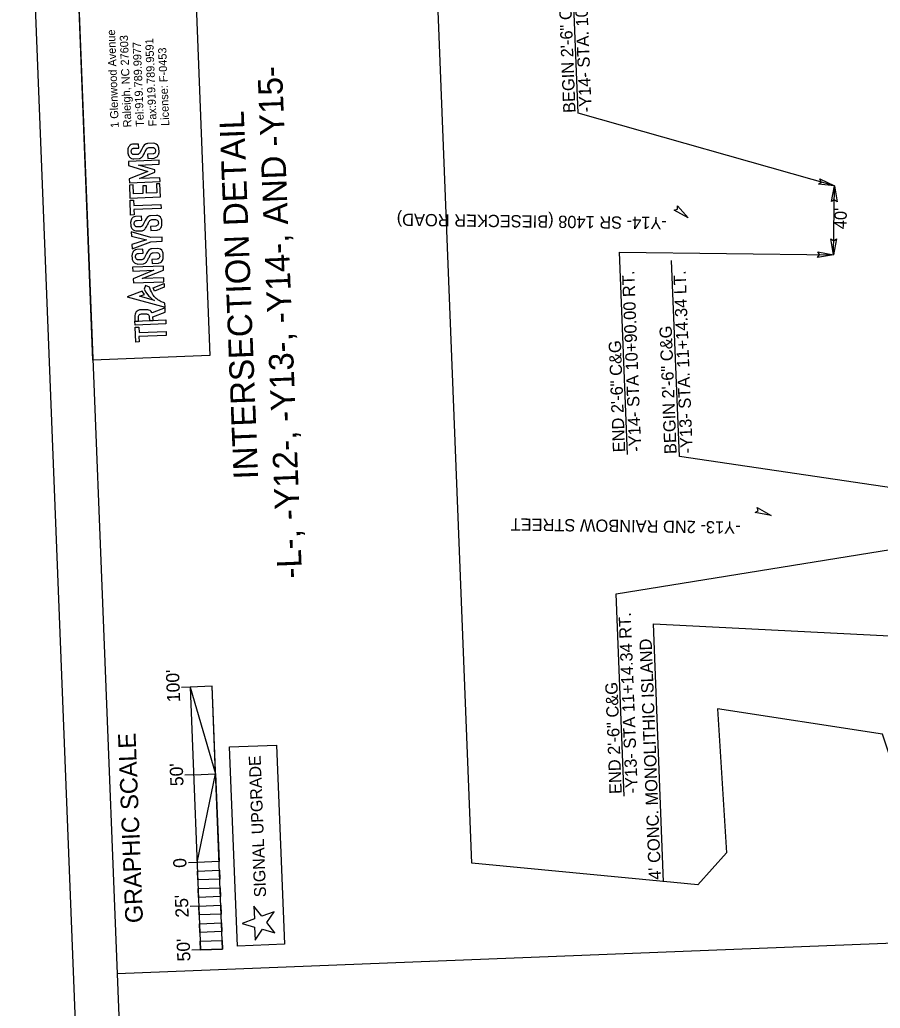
# Model space of a CAD drawing. Extents: x 1627811 to 1628977, y 762656 to 764629.
# Drawn here: x 1627811 to 1628301, y 763561 to 764125 of the extents above; entities that cross this region are included whole.
import ezdxf

# ---------------------------------------------------------------- set-up
doc = ezdxf.new("R2010")
doc.units = 0
for name, color, linetype in [('Old_Level_2', 7, 'Continuous'), ('Old_Level_58', 7, 'Continuous'), ('Prop Dimension', 7, 'Continuous'), ('Prop Dimension Text', 7, 'Continuous'), ('Prop DSN Text', 7, 'Continuous'), ('Prop Grid Mask', 7, 'Continuous'), ('Prop RDY Traffic Signal CELL', 7, 'Continuous'), ('Prop Terminator CELL', 7, 'Continuous'), ('Sheet Clip Boundary CELL', 7, 'Continuous'), ('Sheet Data Field CELL', 7, 'Continuous'), ('Sheet Plan And Profile CELL', 7, 'Continuous'), ('Sheet Plot Border Outside CELL', 7, 'Continuous'), ('Sheet Title CELL', 7, 'Continuous')]:
    doc.layers.add(name, color=color, linetype=linetype)

msp = doc.modelspace()

# ---------------------------------------------------------------- linework, layer by layer
at = {"layer": 'Old_Level_58'}
msp.add_lwpolyline([(1627852.24, 763930.86), (1627844.36, 764130.75), (1627911, 764133.38), (1627918.88, 763933.48)], close=True, dxfattribs=at)
at = {"layer": 'Prop Dimension'}
for p, q in [((1628128.8, 764071.76), (1628124.45, 764182.17)), ((1628274.83, 764030.25), (1628128.8, 764071.76)), ((1628274.32, 763990.99), (1628274.83, 764030.25)), ((1628156.94, 763877.1), (1628152.39, 763992.54)), ((1628152.39, 763992.54), (1628274.32, 763990.99)), ((1628186.47, 763876.05), (1628182.06, 763987.72)), ((1628343.52, 763852.84), (1628186.47, 763876.05)), ((1628150.43, 763797.78), (1628343.17, 763828.84)), ((1628154.98, 763682.34), (1628150.43, 763797.78)), ((1628177.46, 763633.58), (1628171.66, 763780.6)), ((1628171.66, 763780.6), (1628412.51, 763768.42)), ((1627866.03, 763581.23), (1628915.21, 763622.6))]:
    msp.add_line(p, q, dxfattribs=at)
for points in [[(1627878.34, 764051.8), (1627878.25, 764054.11), (1627874.77, 764053.97), (1627874.08, 764053.75), (1627873.5, 764053.44), (1627873.12, 764053.13), (1627872.78, 764052.74), (1627872.52, 764052.3), (1627872.36, 764051.86), (1627872.36, 764051.86), (1627872.19, 764051.4), (1627872.08, 764050.91), (1627872.01, 764050.59), (1627872.12, 764048.84), (1627872.23, 764048.31), (1627872.33, 764047.86), (1627872.59, 764047.41), (1627872.81, 764047.01), (1627873.11, 764046.63), (1627873.44, 764046.33), (1627873.81, 764046.11), (1627874.21, 764045.93), (1627874.92, 764045.7), (1627875.44, 764045.67), (1627878.6, 764045.8), (1627879.08, 764045.93), (1627879.56, 764046.18), (1627879.96, 764046.48), (1627880.26, 764046.79), (1627880.59, 764047.26), (1627880.92, 764047.72), (1627881.12, 764048.01), (1627881.33, 764048.51), (1627881.54, 764049), (1627881.77, 764049.4), (1627882.04, 764049.85), (1627882.29, 764050.39), (1627882.49, 764050.83), (1627882.79, 764051.27), (1627883.07, 764051.59), (1627883.3, 764051.85), (1627883.77, 764052.02), (1627884.07, 764052.13), (1627886.3, 764052.18), (1627886.79, 764052.04), (1627887.22, 764051.81), (1627887.53, 764051.49), (1627887.7, 764051.15), (1627887.79, 764050.81), (1627887.84, 764049.85), (1627887.77, 764049.52), (1627887.59, 764049.19), (1627887.41, 764048.85), (1627887.08, 764048.7), (1627886.75, 764048.54), (1627886.49, 764048.42), (1627883.38, 764048.26), (1627883.5, 764045.92), (1627887.2, 764046.11), (1627887.48, 764046.24), (1627888.33, 764046.54), (1627888.62, 764046.73), (1627888.92, 764047), (1627889.28, 764047.39), (1627889.46, 764047.7), (1627889.63, 764048.15), (1627889.69, 764048.31), (1627889.85, 764048.74), (1627889.89, 764049.28), (1627889.91, 764049.67), (1627889.77, 764051.81), (1627889.61, 764052.4), (1627889.2, 764053.21), (1627889.06, 764053.48), (1627888.25, 764054.07), (1627887.45, 764054.38), (1627886.73, 764054.5), (1627883.32, 764054.32), (1627882.84, 764054.29), (1627882.47, 764054.14), (1627882.13, 764053.94), (1627881.39, 764053.37), (1627880.86, 764052.64), (1627880.32, 764051.64), (1627879.91, 764050.88), (1627879.2, 764049.39), (1627878.67, 764048.61), (1627878.26, 764048.27), (1627877.98, 764048.18), (1627877.7, 764048.09), (1627875.27, 764048.04), (1627875.01, 764048.15), (1627874.75, 764048.27), (1627874.59, 764048.44), (1627874.38, 764048.66), (1627874.27, 764048.92), (1627874.15, 764049.17), (1627874.17, 764049.32), (1627874.1, 764049.33), (1627874.08, 764050.29), (1627874.17, 764050.57), (1627874.27, 764050.85), (1627874.37, 764051.14), (1627874.56, 764051.27), (1627874.83, 764051.47), (1627875.1, 764051.57), (1627875.37, 764051.68), (1627875.68, 764051.68)], [(1627883.56, 764038.47), (1627872.8, 764034.23), (1627872.99, 764032.02), (1627890.44, 764032.8), (1627890.34, 764034.9), (1627878.68, 764034.39), (1627887.53, 764038.01), (1627887.51, 764039.36), (1627878.26, 764042.06), (1627889.97, 764042.57), (1627889.87, 764044.85), (1627872.47, 764044.09), (1627872.57, 764041.8)], [(1627873.01, 764030.67), (1627873.31, 764023.29), (1627890.72, 764024), (1627890.42, 764031.46), (1627888.45, 764031.38), (1627888.65, 764026.34), (1627882.82, 764026.1), (1627882.65, 764030.32), (1627880.57, 764030.23), (1627880.74, 764025.99), (1627875.25, 764025.76), (1627875.05, 764030.77)], [(1627873.69, 764013.61), (1627873.35, 764022.07), (1627875.42, 764022.16), (1627875.55, 764019.05), (1627890.96, 764019.67), (1627891.05, 764017.32), (1627875.54, 764016.7), (1627875.66, 764013.73)], [(1627880, 764010.7), (1627879.91, 764013.01), (1627876.43, 764012.87), (1627875.73, 764012.65), (1627875.16, 764012.34), (1627874.78, 764012.03), (1627874.44, 764011.65), (1627874.18, 764011.2), (1627874.02, 764010.76), (1627874.02, 764010.76), (1627873.84, 764010.3), (1627873.74, 764009.81), (1627873.67, 764009.49), (1627873.78, 764007.74), (1627873.89, 764007.22), (1627873.99, 764006.76), (1627874.25, 764006.31), (1627874.47, 764005.92), (1627874.77, 764005.53), (1627875.1, 764005.24), (1627875.47, 764005.01), (1627875.87, 764004.83), (1627876.58, 764004.6), (1627877.1, 764004.57), (1627880.26, 764004.7), (1627880.73, 764004.83), (1627881.22, 764005.08), (1627881.62, 764005.38), (1627881.92, 764005.69), (1627882.25, 764006.16), (1627882.58, 764006.62), (1627882.78, 764006.92), (1627882.99, 764007.41), (1627883.2, 764007.9), (1627883.43, 764008.3), (1627883.7, 764008.75), (1627883.95, 764009.29), (1627884.15, 764009.73), (1627884.45, 764010.17), (1627884.73, 764010.49), (1627884.96, 764010.75), (1627885.43, 764010.92), (1627885.73, 764011.03), (1627887.96, 764011.08), (1627888.45, 764010.94), (1627888.88, 764010.71), (1627889.19, 764010.4), (1627889.36, 764010.05), (1627889.45, 764009.71), (1627889.5, 764008.75), (1627889.43, 764008.42), (1627889.25, 764008.09), (1627889.07, 764007.75), (1627888.74, 764007.6), (1627888.41, 764007.44), (1627888.15, 764007.32), (1627885.04, 764007.16), (1627885.16, 764004.82), (1627888.86, 764005.01), (1627889.14, 764005.14), (1627889.99, 764005.45), (1627890.28, 764005.63), (1627890.58, 764005.9), (1627890.94, 764006.29), (1627891.12, 764006.6), (1627891.29, 764007.05), (1627891.35, 764007.21), (1627891.51, 764007.64), (1627891.54, 764008.18), (1627891.57, 764008.57), (1627891.43, 764010.71), (1627891.27, 764011.3), (1627890.86, 764012.11), (1627890.72, 764012.38), (1627889.91, 764012.97), (1627889.11, 764013.28), (1627888.39, 764013.4), (1627884.98, 764013.22), (1627884.5, 764013.19), (1627884.13, 764013.04), (1627883.79, 764012.84), (1627883.05, 764012.27), (1627882.52, 764011.54), (1627881.98, 764010.54), (1627881.57, 764009.78), (1627880.86, 764008.29), (1627880.33, 764007.51), (1627879.92, 764007.17), (1627879.64, 764007.08), (1627879.36, 764006.99), (1627876.93, 764006.94), (1627876.67, 764007.06), (1627876.41, 764007.17), (1627876.25, 764007.34), (1627876.04, 764007.57), (1627875.93, 764007.82), (1627875.81, 764008.07), (1627875.83, 764008.22), (1627875.76, 764008.23), (1627875.73, 764009.19), (1627875.83, 764009.47), (1627875.93, 764009.76), (1627876.03, 764010.04), (1627876.22, 764010.17), (1627876.49, 764010.37), (1627876.76, 764010.47), (1627877.03, 764010.58), (1627877.34, 764010.58)], [(1627874.38, 763996.87), (1627874.48, 763994.33), (1627885.21, 763998.38), (1627891.75, 763998.67), (1627891.64, 764001.06), (1627885.16, 764000.77), (1627874.05, 764003.99), (1627874.22, 764001.5), (1627882.65, 763999.52)], [(1627880.76, 763991.85), (1627880.67, 763994.15), (1627877.19, 763994.01), (1627876.5, 763993.79), (1627875.92, 763993.49), (1627875.54, 763993.17), (1627875.2, 763992.79), (1627874.94, 763992.34), (1627874.78, 763991.91), (1627874.78, 763991.91), (1627874.61, 763991.44), (1627874.5, 763990.95), (1627874.43, 763990.63), (1627874.54, 763988.88), (1627874.65, 763988.36), (1627874.75, 763987.91), (1627875.01, 763987.45), (1627875.23, 763987.06), (1627875.53, 763986.68), (1627875.86, 763986.38), (1627876.23, 763986.15), (1627876.63, 763985.97), (1627877.34, 763985.75), (1627877.86, 763985.71), (1627881.03, 763985.84), (1627881.5, 763985.97), (1627881.98, 763986.22), (1627882.38, 763986.53), (1627882.68, 763986.84), (1627883.01, 763987.3), (1627883.34, 763987.77), (1627883.54, 763988.06), (1627883.75, 763988.55), (1627883.96, 763989.04), (1627884.19, 763989.44), (1627884.46, 763989.89), (1627884.71, 763990.43), (1627884.91, 763990.87), (1627885.21, 763991.31), (1627885.49, 763991.64), (1627885.72, 763991.9), (1627886.19, 763992.07), (1627886.49, 763992.17), (1627888.72, 763992.23), (1627889.21, 763992.08), (1627889.64, 763991.86), (1627889.95, 763991.54), (1627890.12, 763991.19), (1627890.21, 763990.85), (1627890.26, 763989.89), (1627890.19, 763989.57), (1627890.01, 763989.23), (1627889.83, 763988.89), (1627889.5, 763988.74), (1627889.17, 763988.58), (1627888.91, 763988.46), (1627885.8, 763988.3), (1627885.92, 763985.97), (1627889.62, 763986.16), (1627889.9, 763986.29), (1627890.75, 763986.59), (1627891.04, 763986.78), (1627891.34, 763987.04), (1627891.7, 763987.44), (1627891.88, 763987.75), (1627892.05, 763988.19), (1627892.11, 763988.35), (1627892.27, 763988.79), (1627892.31, 763989.32), (1627892.33, 763989.72), (1627892.19, 763991.85), (1627892.03, 763992.44), (1627891.62, 763993.25), (1627891.48, 763993.53), (1627890.67, 763994.12), (1627889.87, 763994.42), (1627889.15, 763994.55), (1627885.74, 763994.36), (1627885.26, 763994.33), (1627884.89, 763994.19), (1627884.55, 763993.98), (1627883.81, 763993.41), (1627883.28, 763992.68), (1627882.74, 763991.69), (1627882.33, 763990.93), (1627881.62, 763989.43), (1627881.09, 763988.66), (1627880.68, 763988.31), (1627880.4, 763988.22), (1627880.12, 763988.14), (1627877.69, 763988.09), (1627877.43, 763988.2), (1627877.17, 763988.31), (1627877.01, 763988.49), (1627876.8, 763988.71), (1627876.69, 763988.96), (1627876.57, 763989.22), (1627876.59, 763989.37), (1627876.52, 763989.38), (1627876.5, 763990.34), (1627876.59, 763990.62), (1627876.69, 763990.9), (1627876.79, 763991.18), (1627876.98, 763991.32), (1627877.25, 763991.51), (1627877.52, 763991.62), (1627877.79, 763991.72), (1627878.1, 763991.72)], [(1627875.25, 763974.92), (1627892.7, 763975.62), (1627892.61, 763977.86), (1627880.34, 763977.36), (1627892.46, 763982.29), (1627892.34, 763984.54), (1627874.85, 763983.83), (1627874.94, 763981.65), (1627886.91, 763982.14), (1627875.15, 763977.27)], [(1627871.74, 763967), (1627893.33, 763961.19), (1627893.23, 763963.41), (1627892.37, 763963.71), (1627891.19, 763964.24), (1627890.55, 763964.53), (1627890, 763964.88), (1627889.22, 763965.38), (1627888.74, 763965.68), (1627888.33, 763966.05), (1627887.93, 763966.41), (1627887.41, 763966.88), (1627887.12, 763967.28), (1627886.78, 763967.68), (1627886.43, 763968.22), (1627886.13, 763968.71), (1627885.52, 763969.9), (1627885.07, 763970.88), (1627884.44, 763972.5), (1627882.26, 763973.55), (1627881.39, 763971.34), (1627882.34, 763969.74), (1627883.3, 763968.4), (1627884.13, 763967.46), (1627884.58, 763966.95), (1627885.17, 763966.44), (1627885.75, 763965.93), (1627886.19, 763965.54), (1627886.86, 763965.19), (1627887.22, 763965), (1627878.75, 763967.29), (1627881.6, 763968.4), (1627880.27, 763970.25)], [(1627887.33, 763970.23), (1627886.5, 763972.12), (1627892.84, 763974.64), (1627892.84, 763972.53)], [(1627878.23, 763953.22), (1627878.13, 763955.61), (1627878.17, 763955.91), (1627878.32, 763956.32), (1627878.52, 763956.65), (1627878.79, 763956.9), (1627879.11, 763957.06), (1627879.36, 763957.2), (1627879.94, 763957.22), (1627882.43, 763957.33), (1627882.76, 763957.28), (1627883.21, 763957.21), (1627883.51, 763957.09), (1627883.78, 763956.9), (1627884, 763956.64), (1627884.17, 763956.23), (1627884.22, 763955.9), (1627884.28, 763955.58), (1627884.37, 763953.47), (1627886.48, 763953.57), (1627886.38, 763955.67), (1627893.45, 763958.32), (1627893.33, 763960.73), (1627885.9, 763957.79), (1627885.75, 763958.16), (1627885.33, 763958.68), (1627884.78, 763959.15), (1627884.13, 763959.47), (1627883.49, 763959.66), (1627883.3, 763959.64), (1627878.74, 763959.5), (1627878, 763959.27), (1627877.34, 763958.88), (1627876.88, 763958.45), (1627876.44, 763957.73), (1627876.24, 763957.05), (1627876.04, 763956.36), (1627876.06, 763955.96), (1627876.15, 763953.14)], [(1627876.24, 763950.83), (1627876.15, 763953.14), (1627893.7, 763953.85), (1627893.79, 763951.53)], [(1627876.61, 763941.21), (1627876.27, 763949.67), (1627878.34, 763949.76), (1627878.47, 763946.65), (1627893.88, 763947.27), (1627893.97, 763944.92), (1627878.46, 763944.3), (1627878.58, 763941.33)]]:
    msp.add_lwpolyline(points, close=True, dxfattribs=at)
at = {"layer": 'Prop Grid Mask'}
msp.add_lwpolyline([(1627934.58, 763596.9), (1627930.1, 763710.46), (1627956.85, 763711.51), (1627961.33, 763597.95)], close=True, dxfattribs=at)
at = {"layer": 'Prop RDY Traffic Signal CELL'}
msp.add_lwpolyline([(1627944.39, 763607.77), (1627944.69, 763600.37), (1627948.8, 763606.53), (1627955.94, 763604.52), (1627951.35, 763610.35), (1627955.46, 763616.51), (1627948.51, 763613.94), (1627943.92, 763619.76), (1627944.21, 763612.36), (1627937.25, 763609.78), (1627944.39, 763607.77)], dxfattribs=at)
at = {"layer": 'Prop Terminator CELL'}
for points in [[(1628266.6, 764034.2), (1628274.83, 764030.25), (1628265.69, 764031.19), (1628267.23, 764032.41)], [(1628273.16, 764021.27), (1628274.83, 764030.25), (1628276.31, 764021.18), (1628274.73, 764022.35)], [(1628185.46, 764018.84), (1628191.55, 764012.04), (1628183.46, 764016.4), (1628185.36, 764016.94)], [(1628275.99, 763999.97), (1628274.32, 763990.99), (1628272.84, 764000.06), (1628274.42, 763998.89)], [(1628265.34, 763992.65), (1628274.32, 763990.99), (1628265.25, 763989.5), (1628266.42, 763991.09)], [(1628230.82, 763846.94), (1628238.7, 763842.32), (1628229.66, 763844.01), (1628231.3, 763845.1)]]:
    msp.add_lwpolyline(points, close=True, dxfattribs=at)
at = {"layer": 'Sheet Clip Boundary CELL'}
msp.add_lwpolyline([(1628323.41, 763654.34), (1628302.22, 763717.7), (1628208.23, 763732.1), (1628213.32, 763650), (1628196.97, 763631.82), (1628183.33, 763633.23), (1628068.1, 763644.27), (1628043.63, 764264.81), (1628156.85, 764269.28), (1628154, 764341.74), (1628173.63, 764342.52), (1628176.48, 764270.05), (1628545.1, 764284.59), (1628542.3, 764355.48), (1628560.15, 764356.18), (1628562.95, 764285.29), (1628672.78, 764289.62), (1628669.92, 764362.09), (1628787.91, 764366.75), (1628790.42, 764303.08), (1628811.34, 764303.9), (1628836.16, 763674.56)], close=True, dxfattribs=at)
at = {"layer": 'Sheet Data Field CELL'}
for p, q in [((1627907.66, 763744.55), (1627902.65, 763744.35)), ((1627909.62, 763694.6), (1627904.64, 763694.41)), ((1627912.59, 763619.68), (1627907.6, 763619.49)), ((1627913.57, 763594.71), (1627908.58, 763594.51))]:
    msp.add_line(p, q, dxfattribs=at)
at = {"layer": 'Sheet Plan And Profile CELL'}
msp.add_lwpolyline([(1627836.47, 764330.65), (1627895.58, 762831.81), (1628944.76, 762873.18), (1628885.66, 764372.02)], close=True, dxfattribs=at)
at = {"layer": 'Sheet Plot Border Outside CELL'}
msp.add_lwpolyline([(1628976.64, 762699.3), (1628909.65, 764397.98), (1627810.51, 764354.64), (1627877.49, 762655.96)], close=True, dxfattribs=at)
at = {"layer": 'Sheet Title CELL'}
for p, q in [((1627907.66, 763744.54), (1627902.66, 763744.34)), ((1627920.16, 763745.03), (1627907.66, 763744.54)), ((1627907.66, 763744.54), (1627913.58, 763594.7)), ((1627926.07, 763595.19), (1627920.16, 763745.03)), ((1627909.63, 763694.59), (1627904.65, 763694.39)), ((1627909.63, 763694.59), (1627922.12, 763695.08)), ((1627911.62, 763644.64), (1627906.62, 763644.45)), ((1627912.2, 763629.66), (1627924.68, 763630.15)), ((1627912.6, 763619.67), (1627907.6, 763619.47)), ((1627913.58, 763594.7), (1627908.6, 763594.5)), ((1627908.6, 763594.5), (1627908.6, 763594.5)), ((1627913.58, 763594.7), (1627926.07, 763595.19)), ((1627913.58, 763594.7), (1627913.58, 763594.7))]:
    msp.add_line(p, q, dxfattribs=at)
for points in [[(1627907.66, 763744.54), (1627922.12, 763695.08), (1627920.16, 763745.03)], [(1627911.62, 763644.64), (1627922.12, 763695.08), (1627924.1, 763645.14)], [(1627912, 763634.65), (1627911.8, 763639.65), (1627924.3, 763640.14), (1627924.49, 763635.15)], [(1627912.41, 763624.67), (1627912.2, 763629.66), (1627924.68, 763630.15), (1627924.88, 763625.16)], [(1627912.8, 763614.68), (1627912.6, 763619.67), (1627925.08, 763620.16), (1627925.28, 763615.17)], [(1627913.18, 763604.69), (1627913, 763609.68), (1627925.49, 763610.18), (1627925.68, 763605.19)], [(1627913.58, 763594.7), (1627913.38, 763599.69), (1627925.87, 763600.19), (1627926.07, 763595.19)]]:
    msp.add_lwpolyline(points, close=True, dxfattribs=at)

# ---------------------------------------------------------------- texts
at = {"layer": 'Old_Level_2'}
for s, p in [('1 Glenwood Avenue', (1627866.99, 764063.39)), ('Raleigh, NC 27603', (1627874.18, 764063.67)), ('Fax:919.789.9591', (1627888.56, 764064.24)), ('Tel:919.789.9977 ', (1627881.37, 764063.96)), ('License: F-0453', (1627895.75, 764064.52))]:
    msp.add_text(s, height=4.6576, rotation=92.2582, dxfattribs=at).set_placement(p)
at = {"layer": 'Prop Dimension'}
for s, p in [('-L-, -Y12-, -Y13-, -Y14-, AND -Y15-', (1627971.43, 763806.61)), ('INTERSECTION DETAIL', (1627946.43, 763863.22))]:
    msp.add_text(s, height=14, rotation=92.2582, dxfattribs=at).set_placement(p)
at = {"layer": 'Prop Dimension Text'}
for s, rotation, p in [('-Y14- STA. 10+90.00 LT.', 92.2582, (1628136.49, 764072.32)), ('BEGIN 2\'-6" C&G', 92.2582, (1628127.32, 764071.95)), ("40'", 89.2561, (1628281.77, 764005.5)), ('-Y14- STA 10+90.00 RT.', 92.2582, (1628164.79, 763878.87)), ('-Y13- STA. 11+14.34 LT.', 92.2582, (1628194.11, 763877.87)), ('BEGIN 2\'-6" C&G', 92.2582, (1628184.94, 763877.51)), ('END 2\'-6" C&G', 92.2582, (1628155.62, 763878.51)), ('-Y13- STA 11+14.34 RT.', 92.2582, (1628162.83, 763684.1)), ('END 2\'-6" C&G', 92.2582, (1628153.66, 763683.74))]:
    msp.add_text(s, height=7, rotation=rotation, dxfattribs=at).set_placement(p)
at = {"layer": 'Prop DSN Text'}
for s, height, rotation, p in [('-Y14- SR 1408 (BIESECKER ROAD)', 7, 179.2561, (1628179.36, 764012.47)), ('-Y13- 2ND RAINBOW STREET', 7, 179.1874, (1628221.4, 763838.92)), ("4' CONC. MONOLITHIC ISLAND", 7, 92.2582, (1628176.05, 763634.88)), ('SIGNAL UPGRADE', 6.8072, 92.2582, (1627950.96, 763624.89))]:
    msp.add_text(s, height=height, rotation=rotation, dxfattribs=at).set_placement(p)
at = {"layer": 'Sheet Data Field CELL'}
for s, p in [("100'", (1627901.98, 763736.09)), ("50'", (1627903.88, 763688.21)), ("25'", (1627906.84, 763613.29)), ("50'", (1627907.83, 763588.32))]:
    msp.add_text(s, height=7.498, rotation=92.263, dxfattribs=at).set_placement(p)
at = {"layer": 'Sheet Title CELL'}
for s, height, p in [('GRAPHIC SCALE', 9.9967, (1627880.75, 763610.22)), ('0', 7.5, (1627905.58, 763641.65))]:
    msp.add_text(s, height=height, rotation=92.263, dxfattribs=at).set_placement(p)

doc.saveas('drawing.dxf')
